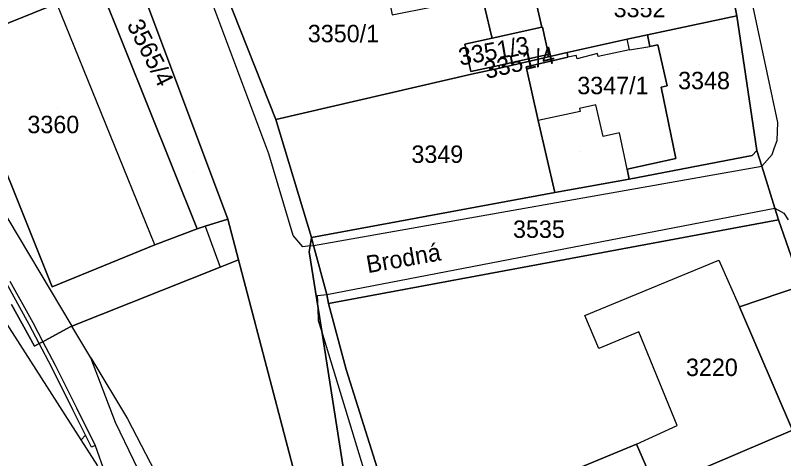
# Model space of a CAD drawing. Extents: x -262657 to -261595, y -1238015 to -1237156.
# Drawn here: x -262030.6 to -261942.4, y -1237748.7 to -1237697.8 of the extents above; entities that cross this region are included whole.
import ezdxf

# ---------------------------------------------------------------- set-up
doc = ezdxf.new("R2010")
doc.units = 0
for name, color, linetype in [('body_kn', 7, 'Continuous'), ('kladpar_druhypozemkov', 7, 'Continuous'), ('kladpar_hranice', 7, 'Continuous'), ('kladpar_parcelnecisla', 7, 'Continuous'), ('kladpar_plochy', 7, 'Continuous'), ('popisy', 7, 'Continuous'), ('zappar_hrandruhpozemk', 7, 'Continuous')]:
    doc.layers.add(name, color=color, linetype=linetype)

msp = doc.modelspace()

# ---------------------------------------------------------------- linework, layer by layer
at = {"layer": 'body_kn'}
for p, q in [((-261947.79, -1237697.89), (-261947.79, -1237697.89)), ((-261947.79, -1237697.89), (-261947.79, -1237697.89)), ((-261970.2, -1237699.2), (-261970.2, -1237699.2)), ((-261970.2, -1237699.2), (-261970.2, -1237699.2)), ((-261970.11, -1237699.18), (-261970.11, -1237699.18)), ((-261975.95, -1237700.18), (-261975.95, -1237700.18)), ((-261958.08, -1237700.07), (-261958.08, -1237700.07)), ((-261979.02, -1237701.14), (-261979.02, -1237701.14)), ((-261975.88, -1237700.45), (-261975.88, -1237700.45)), ((-261960.39, -1237700.58), (-261960.39, -1237700.58)), ((-261960.12, -1237701.79), (-261960.12, -1237701.79)), ((-261957.79, -1237701.39), (-261957.79, -1237701.39)), ((-261956.89, -1237701.23), (-261956.89, -1237701.23)), ((-261969.5, -1237702.34), (-261969.5, -1237702.34)), ((-261969.44, -1237702.61), (-261969.44, -1237702.61)), ((-261969.44, -1237702.61), (-261969.44, -1237702.61)), ((-261969.42, -1237702.32), (-261969.42, -1237702.32)), ((-261967.27, -1237702.11), (-261967.27, -1237702.11)), ((-261967.27, -1237702.11), (-261967.27, -1237702.11)), ((-261967.19, -1237702.64), (-261967.19, -1237702.64)), ((-261966.23, -1237702.42), (-261966.23, -1237702.42)), ((-261966.14, -1237702.82), (-261966.14, -1237702.82)), ((-261963.81, -1237702.22), (-261963.81, -1237702.22)), ((-261963.73, -1237702.54), (-261963.73, -1237702.54)), ((-261975.12, -1237703.57), (-261975.12, -1237703.57)), ((-261972, -1237703.73), (-261972, -1237703.73)), ((-261978.32, -1237704.28), (-261978.32, -1237704.28)), ((-261978.24, -1237704.59), (-261978.24, -1237704.59)), ((-261975.04, -1237703.9), (-261975.04, -1237703.9)), ((-261956.51, -1237706.08), (-261956.51, -1237706.08)), ((-261955.81, -1237705.92), (-261955.81, -1237705.92)), ((-261963.98, -1237708.09), (-261963.98, -1237708.09)), ((-261965.87, -1237708.5), (-261965.87, -1237708.5)), ((-261965.78, -1237708.87), (-261965.78, -1237708.87)), ((-262000.71, -1237709.77), (-262000.71, -1237709.77)), ((-261970.61, -1237709.88), (-261970.61, -1237709.88)), ((-261970.61, -1237709.88), (-261970.61, -1237709.88)), ((-261943.1, -1237710.14), (-261943.1, -1237710.14)), ((-261963.15, -1237711.72), (-261963.15, -1237711.72)), ((-261961.28, -1237711.32), (-261961.28, -1237711.32)), ((-261943.19, -1237712.2), (-261943.19, -1237712.2)), ((-261945.5, -1237713.33), (-261945.5, -1237713.33)), ((-261943.47, -1237712.98), (-261943.47, -1237712.98)), ((-262001.5, -1237713.73), (-262001.5, -1237713.73)), ((-261954.8, -1237714.25), (-261954.8, -1237714.25)), ((-261946.04, -1237713.9), (-261946.04, -1237713.9)), ((-261943.77, -1237713.8), (-261943.77, -1237713.8)), ((-261944.94, -1237715.14), (-261944.94, -1237715.14)), ((-261944.94, -1237715.14), (-261944.94, -1237715.14)), ((-261960.38, -1237715.49), (-261960.38, -1237715.49)), ((-261960.38, -1237715.49), (-261960.38, -1237715.49)), ((-261960.16, -1237716.62), (-261960.16, -1237716.62)), ((-261968.71, -1237718.14), (-261968.71, -1237718.14)), ((-261943.45, -1237719.94), (-261943.45, -1237719.94)), ((-261943.45, -1237719.94), (-261943.45, -1237719.94)), ((-262006.22, -1237721.2), (-262006.22, -1237721.2)), ((-261943.02, -1237721.29), (-261943.02, -1237721.29)), ((-262008.82, -1237722.02), (-262008.82, -1237722.02)), ((-262008.82, -1237722.02), (-262008.82, -1237722.02)), ((-262009.76, -1237722.32), (-262009.76, -1237722.32)), ((-261998.74, -1237723.07), (-261998.74, -1237723.07)), ((-261996.63, -1237723.32), (-261996.63, -1237723.32)), ((-261996.63, -1237723.32), (-261996.63, -1237723.32)), ((-262014.59, -1237724.16), (-262014.59, -1237724.16)), ((-262014.59, -1237724.16), (-262014.59, -1237724.16)), ((-261997.6, -1237724.4), (-261997.6, -1237724.4)), ((-261996.78, -1237724.29), (-261996.78, -1237724.29)), ((-261996.78, -1237724.29), (-261996.78, -1237724.29)), ((-261996.38, -1237724.23), (-261996.38, -1237724.23)), ((-261996.38, -1237724.23), (-261996.38, -1237724.23)), ((-261996.88, -1237724.96), (-261996.88, -1237724.96)), ((-262007.12, -1237726.71), (-262007.12, -1237726.71)), ((-262005, -1237725.87), (-262005, -1237725.87)), ((-261949.89, -1237725.92), (-261949.89, -1237725.92)), ((-262026.4, -1237728.97), (-262026.4, -1237728.97)), ((-261995.92, -1237729.96), (-261995.92, -1237729.96)), ((-261994.88, -1237729.86), (-261994.88, -1237729.86)), ((-261994.88, -1237729.86), (-261994.88, -1237729.86)), ((-261994.68, -1237730.89), (-261994.68, -1237730.89)), ((-261994.68, -1237730.89), (-261994.68, -1237730.89)), ((-261995.86, -1237731.43), (-261995.86, -1237731.43)), ((-261995.86, -1237731.43), (-261995.86, -1237731.43)), ((-261947.49, -1237731.26), (-261947.49, -1237731.26)), ((-261995.81, -1237732.88), (-261995.81, -1237732.88)), ((-261965.26, -1237732.28), (-261965.26, -1237732.28)), ((-262029.01, -1237733.3), (-262029.01, -1237733.3)), ((-262028.6, -1237733.08), (-262028.6, -1237733.08)), ((-262024.32, -1237733.55), (-262024.32, -1237733.55)), ((-262024.14, -1237733.48), (-262024.14, -1237733.48)), ((-261995.45, -1237734.05), (-261995.45, -1237734.05)), ((-261995.45, -1237734.05), (-261995.45, -1237734.05)), ((-261959.07, -1237734.14), (-261959.07, -1237734.14)), ((-262027.86, -1237735.49), (-262027.86, -1237735.49)), ((-262027.86, -1237735.49), (-262027.86, -1237735.49)), ((-262027.46, -1237735.27), (-262027.46, -1237735.27)), ((-262027.46, -1237735.27), (-262027.46, -1237735.27)), ((-262027.19, -1237735.12), (-262027.19, -1237735.12)), ((-262028.41, -1237735.79), (-262028.41, -1237735.79)), ((-261963.65, -1237736.06), (-261963.65, -1237736.06)), ((-262021.95, -1237737.13), (-262021.95, -1237737.13)), ((-262021.95, -1237737.13), (-262021.95, -1237737.13)), ((-262026.44, -1237738.17), (-262026.44, -1237738.17)), ((-262026.05, -1237737.95), (-262026.05, -1237737.95)), ((-261992.63, -1237738.46), (-261992.63, -1237738.46)), ((-262024.01, -1237743.08), (-262024.01, -1237743.08)), ((-262023.58, -1237742.87), (-262023.58, -1237742.87)), ((-262017.75, -1237744.12), (-262017.75, -1237744.12)), ((-262019.11, -1237744.53), (-262019.11, -1237744.53)), ((-261954.64, -1237744.9), (-261954.64, -1237744.9)), ((-262022.56, -1237746), (-262022.56, -1237746)), ((-262023.07, -1237746.54), (-262023.07, -1237746.54)), ((-262023.07, -1237746.54), (-262023.07, -1237746.54)), ((-262021.88, -1237747.37), (-262021.88, -1237747.37)), ((-262021.46, -1237747.17), (-262021.46, -1237747.17)), ((-262021.46, -1237747.17), (-262021.46, -1237747.17)), ((-261959.31, -1237747.04), (-261959.31, -1237747.04)), ((-261959.31, -1237747.04), (-261959.31, -1237747.04))]:
    msp.add_line(p, q, dxfattribs=at)
at = {"layer": 'kladpar_druhypozemkov'}
for p, q in [((-261993.02, -1237698.94), (-261993.02, -1237698.94)), ((-261975.4, -1237700.87), (-261975.4, -1237700.87)), ((-261971.56, -1237702.95), (-261971.56, -1237702.95)), ((-261952.08, -1237703.44), (-261952.08, -1237703.44)), ((-261961.39, -1237704.09), (-261961.39, -1237704.09)), ((-262025.73, -1237708.54), (-262025.73, -1237708.54)), ((-261982.21, -1237713.33), (-261982.21, -1237713.33)), ((-261965.91, -1237713.49), (-261965.91, -1237713.49)), ((-262010.17, -1237715.9), (-262010.17, -1237715.9)), ((-261969.8, -1237721.9), (-261969.8, -1237721.9)), ((-261950.09, -1237737.09), (-261950.09, -1237737.09))]:
    msp.add_line(p, q, dxfattribs=at)
at = {"layer": 'kladpar_hranice'}
for points in [[(-262021.16, -1237749.53), (-262023.07, -1237746.54), (-262062.32, -1237685.22), (-262069, -1237678.62), (-262099.55, -1237648.46), (-262139.84, -1237618.74), (-262199.91, -1237589.44), (-262214.16, -1237582.49), (-262218.71, -1237580.27), (-262317.63, -1237552.02)], [(-261997.77, -1237753.43), (-262005, -1237725.87), (-262006.22, -1237721.2), (-262016.37, -1237694.15), (-262017.13, -1237692.91), (-262019.2, -1237689.5), (-262027.48, -1237675.91), (-262038.27, -1237665.72), (-262070.96, -1237642.62), (-262072.51, -1237641.68), (-262084.62, -1237634.29), (-262143.5, -1237598.35)], [(-262047.43, -1237650.25), (-262043.99, -1237652.9), (-262021.27, -1237670.74), (-262019.03, -1237673.86), (-262018.72, -1237674.53), (-262011.89, -1237684.04), (-262010.26, -1237687.05), (-262006.42, -1237695.36), (-262000.71, -1237709.77), (-261996.63, -1237723.32)], [(-261914.09, -1237816.76), (-261923.62, -1237819.21), (-261923.89, -1237818.34), (-261924, -1237817.96), (-261923.67, -1237817.87), (-261913.97, -1237813.57), (-261908.88, -1237811.31), (-261912.8, -1237801.81), (-261914.12, -1237798.61), (-261922.63, -1237778.24), (-261926.09, -1237769.65), (-261929.76, -1237759.16), (-261940.37, -1237728.85), (-261943.02, -1237721.29), (-261943.45, -1237719.94), (-261944.94, -1237715.14), (-261945.5, -1237713.33), (-261947.79, -1237697.89), (-261949.17, -1237690.86), (-261949.54, -1237688.95), (-261951.01, -1237681.71), (-261952.29, -1237673.66)], [(-262032.25, -1237683.58), (-262029.57, -1237684.79), (-262027.5, -1237686.89), (-262024.3, -1237691.58), (-262023.86, -1237691.4), (-262019.2, -1237689.5), (-262017.13, -1237692.91), (-262020.92, -1237694.46), (-262021.71, -1237694.78), (-262025.86, -1237696.48), (-262036.89, -1237700.92)], [(-261949.17, -1237690.86), (-261970.86, -1237696.21), (-261970.2, -1237699.2), (-261975.88, -1237700.45), (-261975.95, -1237700.18), (-261977.4, -1237694.01), (-261977.44, -1237693.82), (-261971.47, -1237692.6), (-261971.11, -1237694.36), (-261966.37, -1237693.4), (-261954.4, -1237690.63), (-261954.47, -1237690.29), (-261949.54, -1237688.95), (-261949.17, -1237690.86)], [(-262006.42, -1237695.36), (-261989.79, -1237691.43), (-261988.69, -1237691.19), (-261987.37, -1237697.78), (-261982.75, -1237696.85), (-261983.16, -1237694.99), (-261977.44, -1237693.82), (-261977.4, -1237694.01), (-261975.95, -1237700.18), (-261975.88, -1237700.45), (-261979.02, -1237701.14), (-261978.32, -1237704.28), (-261975.12, -1237703.57), (-261975.04, -1237703.9), (-261978.24, -1237704.59), (-262000.71, -1237709.77), (-262006.42, -1237695.36)], [(-261967.27, -1237702.11), (-261969.44, -1237702.61), (-261969.5, -1237702.34), (-261969.42, -1237702.32), (-261970.11, -1237699.18), (-261970.2, -1237699.2), (-261970.86, -1237696.21), (-261949.17, -1237690.86), (-261947.79, -1237697.89), (-261958.08, -1237700.07), (-261960.39, -1237700.58), (-261967.27, -1237702.11)], [(-262017.13, -1237692.91), (-262016.37, -1237694.15), (-262006.22, -1237721.2), (-262008.82, -1237722.02), (-262009.76, -1237722.32), (-262020.92, -1237694.46), (-262017.13, -1237692.91)], [(-262040.03, -1237706.38), (-262043.06, -1237698.94), (-262038.4, -1237697.11), (-262036.89, -1237700.92), (-262025.86, -1237696.48), (-262021.71, -1237694.78), (-262020.92, -1237694.46), (-262009.76, -1237722.32), (-262014.59, -1237724.16), (-262026.4, -1237728.97), (-262036.16, -1237704.61), (-262040.03, -1237706.38)], [(-261947.79, -1237697.89), (-261945.5, -1237713.33), (-261946.04, -1237713.9), (-261960.16, -1237716.62), (-261960.38, -1237715.49), (-261954.8, -1237714.25), (-261956.51, -1237706.08), (-261955.81, -1237705.92), (-261956.89, -1237701.23), (-261957.79, -1237701.39), (-261958.08, -1237700.07), (-261947.79, -1237697.89)], [(-261970.2, -1237699.2), (-261970.11, -1237699.18), (-261969.42, -1237702.32), (-261969.5, -1237702.34), (-261975.12, -1237703.57), (-261978.32, -1237704.28), (-261979.02, -1237701.14), (-261975.88, -1237700.45), (-261970.2, -1237699.2)], [(-261970.61, -1237709.88), (-261972, -1237703.73), (-261967.19, -1237702.64), (-261967.27, -1237702.11), (-261960.39, -1237700.58), (-261958.08, -1237700.07), (-261957.79, -1237701.39), (-261956.89, -1237701.23), (-261955.81, -1237705.92), (-261956.51, -1237706.08), (-261954.8, -1237714.25), (-261960.38, -1237715.49), (-261960.16, -1237716.62), (-261968.71, -1237718.14), (-261970.61, -1237709.88)], [(-261996.63, -1237723.32), (-262000.71, -1237709.77), (-261978.24, -1237704.59), (-261975.04, -1237703.9), (-261969.44, -1237702.61), (-261967.27, -1237702.11), (-261967.19, -1237702.64), (-261972, -1237703.73), (-261970.61, -1237709.88), (-261968.71, -1237718.14), (-261996.63, -1237723.32)], [(-261969.44, -1237702.61), (-261975.04, -1237703.9), (-261975.12, -1237703.57), (-261969.5, -1237702.34), (-261969.44, -1237702.61)], [(-262036.16, -1237704.61), (-262026.4, -1237728.97), (-262014.59, -1237724.16), (-262009.76, -1237722.32), (-262008.82, -1237722.02), (-262006.22, -1237721.2), (-262005, -1237725.87), (-262007.12, -1237726.71), (-262024.14, -1237733.48), (-262024.32, -1237733.55), (-262027.19, -1237735.12), (-262027.46, -1237735.27), (-262027.86, -1237735.49), (-262028.41, -1237735.79), (-262031.04, -1237731.01)], [(-261996.63, -1237723.32), (-261968.71, -1237718.14), (-261960.16, -1237716.62), (-261946.04, -1237713.9), (-261945.5, -1237713.33), (-261944.94, -1237715.14), (-261943.45, -1237719.94), (-261943.02, -1237721.29), (-261994.68, -1237730.89), (-261994.88, -1237729.86), (-261996.38, -1237724.23), (-261996.63, -1237723.32)], [(-261986.41, -1237758.24), (-261992.63, -1237738.46), (-261994.68, -1237730.89), (-261943.02, -1237721.29), (-261940.37, -1237728.85), (-261947.49, -1237731.26), (-261941.42, -1237745.41), (-261957.12, -1237752.11), (-261959.31, -1237747.04), (-261986.41, -1237758.24)], [(-261981.16, -1237826.07), (-261981.69, -1237822.6), (-261989.56, -1237771.61), (-261995.45, -1237734.05), (-261995.86, -1237731.43), (-261996.88, -1237724.96), (-261996.78, -1237724.29), (-261996.63, -1237723.32)], [(-261996.63, -1237723.32), (-261996.78, -1237724.29), (-261996.88, -1237724.96), (-261995.86, -1237731.43), (-261995.45, -1237734.05), (-261989.56, -1237771.61), (-261981.69, -1237822.6), (-261981.16, -1237826.07)], [(-261996.63, -1237723.32), (-261996.38, -1237724.23), (-261994.88, -1237729.86), (-261994.68, -1237730.89)], [(-262031.04, -1237731.01), (-262028.41, -1237735.79), (-262027.86, -1237735.49), (-262027.46, -1237735.27), (-262027.19, -1237735.12), (-262024.32, -1237733.55), (-262024.14, -1237733.48), (-262007.12, -1237726.71), (-262005, -1237725.87), (-261997.77, -1237753.43)], [(-261979.29, -1237780.53), (-261986.41, -1237758.24), (-261959.31, -1237747.04), (-261957.12, -1237752.11), (-261941.42, -1237745.41), (-261947.49, -1237731.26), (-261940.37, -1237728.85), (-261929.76, -1237759.16), (-261926.09, -1237769.65), (-261979.29, -1237780.53)], [(-261994.68, -1237730.89), (-261992.63, -1237738.46), (-261986.41, -1237758.24), (-261979.29, -1237780.53), (-261974.24, -1237797.56), (-261981.16, -1237826.07)]]:
    msp.add_lwpolyline(points, dxfattribs=at)
at = {"layer": 'kladpar_plochy'}
for points in [[(-262021.16, -1237749.53), (-262023.07, -1237746.54), (-262062.32, -1237685.22), (-262069, -1237678.62), (-262099.55, -1237648.46), (-262139.84, -1237618.74), (-262199.91, -1237589.44), (-262214.16, -1237582.49), (-262218.71, -1237580.27), (-262317.63, -1237552.02)], [(-262043.99, -1237652.9), (-262021.27, -1237670.74), (-262019.03, -1237673.86), (-262018.72, -1237674.53), (-262011.89, -1237684.04), (-262010.26, -1237687.05), (-262006.42, -1237695.36), (-262000.71, -1237709.77), (-261996.63, -1237723.32), (-261996.78, -1237724.29), (-261996.88, -1237724.96), (-261995.86, -1237731.43), (-261995.45, -1237734.05), (-261989.56, -1237771.61)], [(-261997.77, -1237753.43), (-262005, -1237725.87), (-262006.22, -1237721.2), (-262016.37, -1237694.15), (-262017.13, -1237692.91), (-262019.2, -1237689.5), (-262027.48, -1237675.91), (-262038.27, -1237665.72)], [(-261940.37, -1237728.85), (-261943.02, -1237721.29), (-261943.45, -1237719.94), (-261944.94, -1237715.14), (-261945.5, -1237713.33), (-261947.79, -1237697.89), (-261949.17, -1237690.86), (-261949.54, -1237688.95), (-261951.01, -1237681.71), (-261952.29, -1237673.66), (-261950.91, -1237673.28), (-261944.34, -1237671.48), (-261942.75, -1237671.05), (-261942.23, -1237673.66)], [(-262032.25, -1237683.58), (-262029.57, -1237684.79), (-262027.5, -1237686.89), (-262024.3, -1237691.58), (-262023.86, -1237691.4), (-262019.2, -1237689.5), (-262017.13, -1237692.91), (-262020.92, -1237694.46), (-262021.71, -1237694.78), (-262025.86, -1237696.48), (-262036.89, -1237700.92)], [(-262036.16, -1237704.61), (-262026.4, -1237728.97), (-262014.59, -1237724.16), (-262009.76, -1237722.32), (-262008.82, -1237722.02), (-262006.22, -1237721.2), (-262005, -1237725.87), (-262007.12, -1237726.71), (-262024.14, -1237733.48), (-262024.32, -1237733.55), (-262027.19, -1237735.12), (-262027.46, -1237735.27), (-262027.86, -1237735.49), (-262028.41, -1237735.79), (-262031.04, -1237731.01)], [(-262031.04, -1237731.01), (-262028.41, -1237735.79), (-262027.86, -1237735.49), (-262027.46, -1237735.27), (-262027.19, -1237735.12), (-262024.32, -1237733.55), (-262024.14, -1237733.48), (-262007.12, -1237726.71), (-262005, -1237725.87), (-261997.77, -1237753.43)]]:
    msp.add_lwpolyline(points, dxfattribs=at)
for points in [[(-261949.17, -1237690.86), (-261970.86, -1237696.21), (-261970.2, -1237699.2), (-261975.88, -1237700.45), (-261975.95, -1237700.18), (-261977.4, -1237694.01), (-261977.44, -1237693.82), (-261971.47, -1237692.6), (-261971.11, -1237694.36), (-261966.37, -1237693.4), (-261954.4, -1237690.63), (-261954.47, -1237690.29), (-261949.54, -1237688.95)], [(-262006.42, -1237695.36), (-261989.79, -1237691.43), (-261988.69, -1237691.19), (-261987.37, -1237697.78), (-261982.75, -1237696.85), (-261983.16, -1237694.99), (-261977.44, -1237693.82), (-261977.4, -1237694.01), (-261975.95, -1237700.18), (-261975.88, -1237700.45), (-261979.02, -1237701.14), (-261978.32, -1237704.28), (-261975.12, -1237703.57), (-261975.04, -1237703.9), (-261978.24, -1237704.59), (-262000.71, -1237709.77)], [(-261967.27, -1237702.11), (-261969.44, -1237702.61), (-261969.5, -1237702.34), (-261969.42, -1237702.32), (-261970.11, -1237699.18), (-261970.2, -1237699.2), (-261970.86, -1237696.21), (-261949.17, -1237690.86), (-261947.79, -1237697.89), (-261958.08, -1237700.07), (-261960.39, -1237700.58)], [(-262017.13, -1237692.91), (-262016.37, -1237694.15), (-262006.22, -1237721.2), (-262008.82, -1237722.02), (-262009.76, -1237722.32), (-262020.92, -1237694.46)], [(-262040.03, -1237706.38), (-262043.06, -1237698.94), (-262038.4, -1237697.11), (-262036.89, -1237700.92), (-262025.86, -1237696.48), (-262021.71, -1237694.78), (-262020.92, -1237694.46), (-262009.76, -1237722.32), (-262014.59, -1237724.16), (-262026.4, -1237728.97), (-262036.16, -1237704.61)], [(-261947.79, -1237697.89), (-261945.5, -1237713.33), (-261946.04, -1237713.9), (-261960.16, -1237716.62), (-261960.38, -1237715.49), (-261954.8, -1237714.25), (-261956.51, -1237706.08), (-261955.81, -1237705.92), (-261956.89, -1237701.23), (-261957.79, -1237701.39), (-261958.08, -1237700.07)], [(-261970.2, -1237699.2), (-261970.11, -1237699.18), (-261969.42, -1237702.32), (-261969.5, -1237702.34), (-261975.12, -1237703.57), (-261978.32, -1237704.28), (-261979.02, -1237701.14), (-261975.88, -1237700.45)], [(-261970.61, -1237709.88), (-261972, -1237703.73), (-261967.19, -1237702.64), (-261967.27, -1237702.11), (-261960.39, -1237700.58), (-261958.08, -1237700.07), (-261957.79, -1237701.39), (-261956.89, -1237701.23), (-261955.81, -1237705.92), (-261956.51, -1237706.08), (-261954.8, -1237714.25), (-261960.38, -1237715.49), (-261960.16, -1237716.62), (-261968.71, -1237718.14)], [(-261996.63, -1237723.32), (-262000.71, -1237709.77), (-261978.24, -1237704.59), (-261975.04, -1237703.9), (-261969.44, -1237702.61), (-261967.27, -1237702.11), (-261967.19, -1237702.64), (-261972, -1237703.73), (-261970.61, -1237709.88), (-261968.71, -1237718.14)], [(-261969.44, -1237702.61), (-261975.04, -1237703.9), (-261975.12, -1237703.57), (-261969.5, -1237702.34)], [(-261996.63, -1237723.32), (-261968.71, -1237718.14), (-261960.16, -1237716.62), (-261946.04, -1237713.9), (-261945.5, -1237713.33), (-261944.94, -1237715.14), (-261943.45, -1237719.94), (-261943.02, -1237721.29), (-261994.68, -1237730.89), (-261994.88, -1237729.86), (-261996.38, -1237724.23)], [(-261986.41, -1237758.24), (-261992.63, -1237738.46), (-261994.68, -1237730.89), (-261943.02, -1237721.29), (-261940.37, -1237728.85), (-261947.49, -1237731.26), (-261941.42, -1237745.41), (-261957.12, -1237752.11), (-261959.31, -1237747.04)], [(-261994.68, -1237730.89), (-261992.63, -1237738.46), (-261986.41, -1237758.24), (-261979.29, -1237780.53), (-261974.24, -1237797.56), (-261981.16, -1237826.07), (-261981.69, -1237822.6), (-261989.56, -1237771.61), (-261995.45, -1237734.05), (-261995.86, -1237731.43), (-261996.88, -1237724.96), (-261996.78, -1237724.29), (-261996.63, -1237723.32), (-261996.38, -1237724.23), (-261994.88, -1237729.86)], [(-261979.29, -1237780.53), (-261986.41, -1237758.24), (-261959.31, -1237747.04), (-261957.12, -1237752.11), (-261941.42, -1237745.41), (-261947.49, -1237731.26), (-261940.37, -1237728.85), (-261929.76, -1237759.16), (-261926.09, -1237769.65)]]:
    msp.add_lwpolyline(points, close=True, dxfattribs=at)
at = {"layer": 'zappar_hrandruhpozemk'}
for p, q in [((-261943.1, -1237710.14), (-261950.91, -1237673.28)), ((-262014.59, -1237724.16), (-262025.86, -1237696.48)), ((-261960.12, -1237701.79), (-261960.39, -1237700.58)), ((-261960.12, -1237701.79), (-261963.73, -1237702.54)), ((-261960.12, -1237701.79), (-261957.79, -1237701.39)), ((-262040.59, -1237705.95), (-262024.14, -1237733.48)), ((-261963.15, -1237711.72), (-261963.98, -1237708.09)), ((-261996.38, -1237724.23), (-261944.94, -1237715.14)), ((-261994.88, -1237729.86), (-261943.45, -1237719.94)), ((-262008.82, -1237722.02), (-262007.12, -1237726.71)), ((-261996.78, -1237724.29), (-261996.38, -1237724.23)), ((-261965.26, -1237732.28), (-261949.89, -1237725.92)), ((-261949.89, -1237725.92), (-261947.49, -1237731.26)), ((-261995.92, -1237729.96), (-261994.88, -1237729.86)), ((-261995.86, -1237731.43), (-261995.92, -1237729.96)), ((-261995.81, -1237732.88), (-261995.86, -1237731.43)), ((-261995.45, -1237734.05), (-261995.81, -1237732.88)), ((-261976.28, -1237797.03), (-261995.45, -1237734.05)), ((-262026.44, -1237738.17), (-262027.86, -1237735.49)), ((-262027.46, -1237735.27), (-262026.05, -1237737.95)), ((-262023.07, -1237746.54), (-262022.56, -1237746)), ((-262021.46, -1237747.17), (-262020.34, -1237750.31))]:
    msp.add_line(p, q, dxfattribs=at)
for points in [[(-261996.78, -1237724.29), (-261997.6, -1237724.4), (-261998.74, -1237723.07), (-262001.5, -1237713.73), (-262010.12, -1237690.73)], [(-261963.73, -1237702.54), (-261963.81, -1237702.22), (-261966.14, -1237702.82), (-261966.23, -1237702.42), (-261967.19, -1237702.64)], [(-261963.98, -1237708.09), (-261965.87, -1237708.5), (-261965.78, -1237708.87), (-261970.61, -1237709.88)], [(-261944.94, -1237715.14), (-261943.77, -1237713.8), (-261943.47, -1237712.98), (-261943.19, -1237712.2), (-261943.1, -1237710.14)], [(-261960.38, -1237715.49), (-261961.28, -1237711.32), (-261963.15, -1237711.72)], [(-261943.45, -1237719.94), (-261942.43, -1237720.52), (-261941.9, -1237721.28)], [(-262027.86, -1237735.49), (-262029.01, -1237733.3), (-262031.63, -1237728.56), (-262034.42, -1237723.83)], [(-262031.24, -1237728.32), (-262028.6, -1237733.08), (-262027.46, -1237735.27)], [(-261959.31, -1237747.04), (-261954.64, -1237744.9), (-261959.07, -1237734.14), (-261963.65, -1237736.06), (-261965.26, -1237732.28)], [(-262014.92, -1237753.27), (-262019.11, -1237744.53), (-262021.95, -1237737.13), (-262024.14, -1237733.48)], [(-262021.95, -1237737.13), (-262017.75, -1237744.12), (-262013.57, -1237752.16)], [(-262026.05, -1237737.95), (-262023.58, -1237742.87), (-262021.46, -1237747.17), (-262021.88, -1237747.37), (-262022.56, -1237746), (-262024.01, -1237743.08), (-262026.44, -1237738.17)]]:
    msp.add_lwpolyline(points, dxfattribs=at)

# ---------------------------------------------------------------- texts
at = {"layer": 'kladpar_parcelnecisla'}
for s, p in [('3352', (-261961.947, -1237698.05)), ('3350/1', (-261997.042, -1237700.92)), ('3348', (-261954.548, -1237706.31)), ('3347/1', (-261966.118, -1237706.88)), ('3360', (-262029.226, -1237711.35)), ('3349', (-261985.155, -1237714.76)), ('3535', (-261973.495, -1237723.36)), ('3220', (-261953.647, -1237739.21))]:
    msp.add_text(s, height=2, dxfattribs=at).set_placement(p)
for s, rotation, p in [('3565/4', 297, (-262017.859, -1237698.913)), ('3351/3', 10, (-261979.566, -1237703.599)), ('3351/4', 13, (-261976.535, -1237705.132))]:
    msp.add_text(s, height=2, rotation=rotation, dxfattribs=at).set_placement(p)
at = {"layer": 'popisy'}
msp.add_text('Brodná', height=2, rotation=10, dxfattribs=at).set_placement((-261990.151, -1237727.417))

doc.saveas('drawing.dxf')
